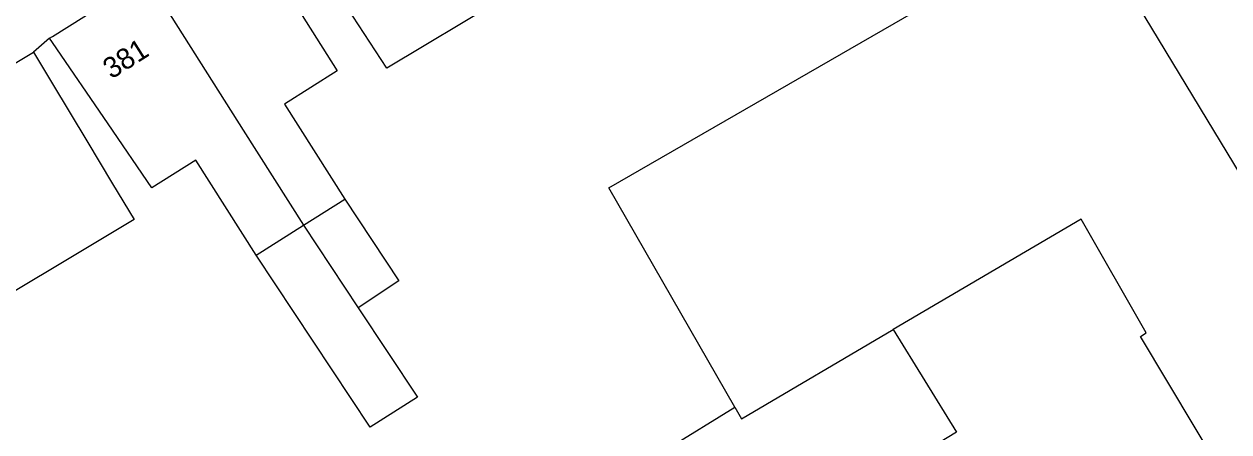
# Model space of a CAD drawing. Extents: x 159222 to 160346, y 381249 to 382166.
# Drawn here: x 159998.6 to 160056.7, y 381586.7 to 381606.3 of the extents above; entities that cross this region are included whole.
import ezdxf

# ---------------------------------------------------------------- set-up
doc = ezdxf.new("R2010")
doc.units = 0
for name, color, linetype in [('IMGEO_Pand', 7, 'Continuous'), ('IMGEO_Pand_nummerreeks', 7, 'Continuous'), ('IMGEO_Voetpad_open', 7, 'Continuous')]:
    doc.layers.add(name, color=color, linetype=linetype)

msp = doc.modelspace()

# ---------------------------------------------------------------- linework, layer by layer
at = {"layer": 'IMGEO_Pand'}
for points in [[(160021.972, 381607.729), (160022.057, 381607.546), (160021.691, 381607.322), (160021.586, 381607.497), (160016.102, 381604.209), (160013.373, 381608.417), (160010.653, 381612.612)], [(160009.048, 381611.466), (160011.718, 381607.239), (160013.711, 381604.084), (160011.177, 381602.484), (160014.078, 381597.892)], [(160032.866, 381587.856), (160026.803, 381598.447), (160049.627, 381611.625), (160059.237, 381595.737), (160060.16, 381596.34), (160064.034, 381590.405)], [(159999.858, 381605.66), (160000, 381605.75), (160004.524, 381608.608)], [(160004.524, 381608.608), (160009.187, 381601.226), (160012.087, 381596.635)], [(160009.804, 381595.193), (160006.904, 381599.784), (160004.792, 381598.449), (160002.682, 381601.534), (160000, 381605.453), (159999.858, 381605.66)], [(159999.082, 381604.99), (160000, 381603.46), (160001.655, 381600.703), (160002.895, 381598.634), (160003.926, 381596.913), (160000, 381594.557), (159997.606, 381593.12), (159996.573, 381594.842), (159995.332, 381596.91), (159992.76, 381601.198)], [(159992.76, 381601.198), (159999.082, 381604.99)], [(160012.087, 381596.635), (160014.078, 381597.892)], [(160014.078, 381597.892), (160016.683, 381593.956), (160014.72, 381592.657)], [(160009.804, 381595.193), (160012.087, 381596.635)], [(160012.087, 381596.635), (160014.72, 381592.657)], [(160053.781, 381582.955), (160056.352, 381584.668), (160052.409, 381591.278), (160052.674, 381591.451), (160049.549, 381596.935), (160040.486, 381591.604)], [(160014.72, 381592.657), (160017.575, 381588.342), (160015.293, 381586.9), (160009.804, 381595.193)], [(160040.486, 381591.604), (160043.542, 381586.659), (160042.278, 381585.878), (160042.135, 381586.111), (160029.854, 381578.522)], [(160032.866, 381587.856), (160033.181, 381587.306), (160040.486, 381591.604)], [(160028.829, 381579.954), (160026.411, 381583.867), (160032.866, 381587.856)]]:
    msp.add_lwpolyline(points, dxfattribs=at)
at = {"layer": 'IMGEO_Voetpad_open'}
msp.add_lwpolyline([(159999.858, 381605.66), (159999.082, 381604.99)], dxfattribs=at)

# ---------------------------------------------------------------- texts
at = {"layer": 'IMGEO_Pand_nummerreeks'}
msp.add_text('381', height=1, rotation=32.28617, dxfattribs=at).set_placement((160002.838, 381603.663))

doc.saveas('drawing.dxf')
